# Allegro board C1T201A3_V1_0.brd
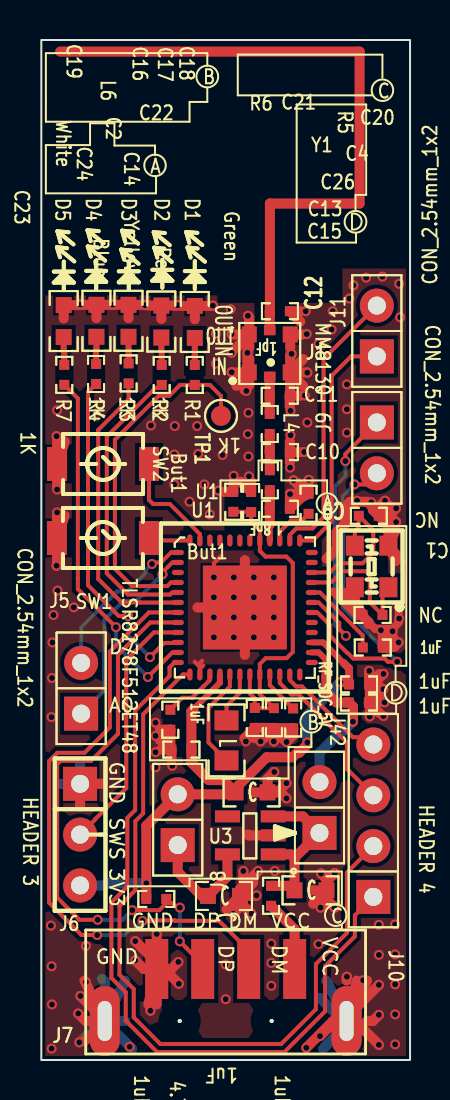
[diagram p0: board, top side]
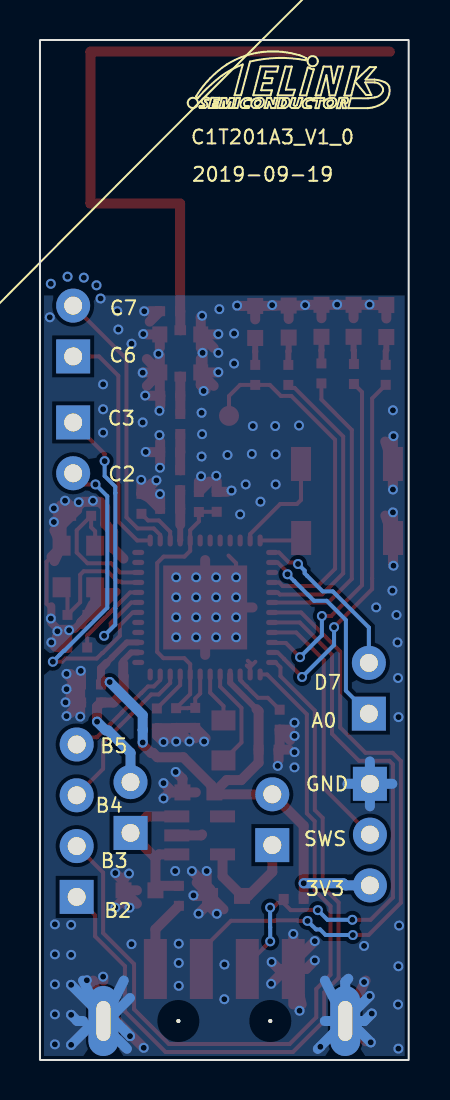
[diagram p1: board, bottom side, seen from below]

Outline 18.45 x 51 mm; copper layers: TOP, BOTTOM. Coordinates in mm from the lower left corner of the outline.
Outline path: rectangle 0,0 18.45,51

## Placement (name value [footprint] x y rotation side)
C1  NC  [0402]  16.39 27.21 0 top
C2  2.2uF  [0402]  10.5 27.9 270 top
C4  NC  [0402]  16.57 22.25 180 top
C9  NC  [0402]  11.94 27.56 180 top
C10  1.2pF  [0402]  11.94 30.39 180 top
C11  2.4pF  [0402]  11.93 33.21 180 top
C12  1pF  [0402]  11.94 37.44 180 top
C13  1uF  [0402]  15.9 18.78 0 top
C14  1uF  [0402]  13.37 27.81 270 top
C15  1uF  [0402]  15.89 17.88 0 top
C16  1uF  [0402]  10.68 17.1 90 top
C17  0.1uF  [0402]  11.64 17.09 90 top
C18  1uF  [0402]  12.6 17.08 270 top
C19  1uF  [0402]  6.46 17.01 90 top
C20  10uF  [0603C]  13.47 8.48 0 top
C21  10uF  [0603C]  9.14 8.2 0 top
C22  10uF  [0603C]  10.52 13.38 0 top
C23  0.1uF  [0402]  9.61 27.91 270 top
C24  220pf  [0402]  11.44 28.99 90 top
C25  1uF  [0402]  7.01 15.52 0 top
C26  1uF  [0402]  16.59 20.62 0 top
D1  Green  [0603-LED]  7.68 36.9 90 top
D2  Red  [0603-LED]  6.01 36.92 90 top
D3  Yellow  [0603-LED]  4.36 36.96 90 top
D4  Blue  [0603-LED]  2.76 36.96 90 top
D5  White  [0603-LED]  1.12 36.95 90 top
J1  MM8130  [MM8130-2600]  11.43 35.33 180 top
J5  CON_2.54mm_1x2  [HDR254F-1X2X850]  1.99 19.86 270 top
J6  HEADER 3  [HDR254M-1X3]  1.94 13.81 270 top
J7  USB_SMT_4PIN  [USB-M-4]  9.22 4.55 90 top
J8  B2S  [HDR254F-1X2X850]  6.83 13.28 270 top
J9  CON_2.54mm_1x2  [HDR254F-1X2X850]  16.79 29.34 90 top
J10  HEADER 4  [HDR254F-1X4X850]  16.61 15.78 270 top
J11  CON_2.54mm_1x2  [HDR254F-1X2X850]  16.79 37.72 270 top
J42  RF_SOC_5V  [HDR254F-1X2X850]  13.92 13.89 270 top
L4  2.4nH  [0402]  11.43 31.8 90 top
L6  4.7uH  [0805L]  9.27 15.98 270 top
R1  1K  [0402]  7.68 34.25 90 top
R2  1K  [0402]  6.02 34.25 90 top
R3  1K  [0402]  4.37 34.33 90 top
R4  1K  [0402]  2.74 34.3 90 top
R5  10  [0402]  11.5 8.21 90 top
R6  NC/1.5K  [0402]  5.75 8.05 0 top
R7  1K  [0402]  1.15 34.26 90 top
SW1  But1  [BUTSMD2PX4_00Y3_00_NH]  3.08 26.1 270 top
SW2  But1  [BUTSMD2PX4_00Y3_00_NH]  3.09 29.8 270 top
TP1  A2  [TP100]  8.99 32.21 0 top
U1  TLSR8278F512ET48  [QFN_7X7_48PIN_0P5_4P20X4P20]  10.18 22.63 0 top
U3  XC6219_3.3V_SOT-23-5  [SOT-23-5]  10.46 11.23 90 top
Y1  24MHz-12pF-+/-20ppm  [OSCCC200X250X080]  16.53 24.68 180 top

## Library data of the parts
C1 C4 = C1005_NC
C2 C13-C15 C23 C24 C26 = C1005X5R1C104K
C9-C12 = C1608_NC
C16 C17 C19 C25 = C1005X5R1C105K
C18 C20-C22 = C1608X5R0J106M
D1-D5 = 0603D_Red
J1 = MM8130
J5 J9 J11 = CON_2.54mm_1x2: User Part Number: pn; Tolerance: RichardLC
J6 = HEADER 3: User Part Number: pn; Tolerance: RichardLC
J7 = USB_SMT_1
J8 = B2S_0: User Part Number: pn; Tolerance: RichardLC
J10 = HEADER_4: User Part Number: pn; Tolerance: RichardLC
J42 = B2S_3: User Part Number: pn; Tolerance: RichardLC
L4 = MLK1608_000R
L6 = IND_0
R1-R4 R7 = RS0402K332JT
R5 R6 = RS0402K100JT
SW1 SW2 = SW2PIN_3x4
TP1 = TestPad100
U1 = TLSR8278F1KET48_2
U3 = XC6219_1.3V_SOT-23-5
Y1 = OSC_25x32_4pin

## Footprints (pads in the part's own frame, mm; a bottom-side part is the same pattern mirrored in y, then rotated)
0402
  rect 0.5x0.5 smd: 1(-0.5,0) 2(0.5,0)
0603-LED
  rect 0.8x0.8 smd: A(-0.8,0) C(0.8,0)
0603C
  rect 0.8x0.8 smd: 1(-0.8,0) 2(0.8,0)
0805L
  rect 1x1.2 smd: 1(-1,0) 2(1,0)
BUTSMD2PX4_00Y3_00_NH
  rect 1.7x1 smd: 1(0,2.3) 2(0,-2.3)
HDR254F-1X2X850
  rect 1.7x1.7 hole 0.9: 1(2.54,0)
  round 1.7 hole 0.9: 2(0,0)
HDR254F-1X4X850
  rect 1.7x1.7 hole 0.9: 1(7.62,0)
  round 1.7 hole 0.9: 2(5.08,0) 3(2.54,0) 4(0,0)
HDR254M-1X3
  rect 1.7x1.7 hole 0.9: 1(0,0)
  round 1.7 hole 0.9: 2(2.54,0) 3(5.08,0)
MM8130-2600
  rect 0.58x0.5 smd: 1(0,1.16) 2(0,-1.16)
  rect 0.75x0.8 smd: 3(-1.025,0.95) 4(1.025,0.95) 5(-1.025,-0.95) 6(1.025,-0.95)
OSCCC200X250X080
  rect 0.9x1 smd: 1(-0.84,1.04) 2(-0.84,-1.04) 3(0.84,-1.04) 4(0.84,1.04)
QFN_7X7_48PIN_0P5_4P20X4P20
  oval 0.6x0.26 smd: 1(-3.35,2.75) 2(-3.35,2.25) 3(-3.35,1.75) 4(-3.35,1.25) 5(-3.35,0.75) 6(-3.35,0.25) 7(-3.35,-0.25) 8(-3.35,-0.75) 9(-3.35,-1.25) 10(-3.35,-1.75) 11(-3.35,-2.25) 12(-3.35,-2.75) 25(3.35,-2.75) 26(3.35,-2.25) 27(3.35,-1.75) 28(3.35,-1.25) 29(3.35,-0.75) 30(3.35,-0.25) 31(3.35,0.25) 32(3.35,0.75) 33(3.35,1.25) 34(3.35,1.75) 35(3.35,2.25) 36(3.35,2.75)
  oval 0.26x0.6 smd: 13(-2.75,-3.35) 14(-2.25,-3.35) 15(-1.75,-3.35) 16(-1.25,-3.35) 17(-0.75,-3.35) 18(-0.25,-3.35) 19(0.25,-3.35) 20(0.75,-3.35) 21(1.25,-3.35) 22(1.75,-3.35) 23(2.25,-3.35) 24(2.75,-3.35) 37(2.75,3.35) 38(2.25,3.35) 39(1.75,3.35) 40(1.25,3.35) 41(0.75,3.35) 42(0.25,3.35) 43(-0.25,3.35) 44(-0.75,3.35) 45(-1.25,3.35) 46(-1.75,3.35) 47(-2.25,3.35) 48(-2.75,3.35)
  rect 4.2x4.2 smd: 49(0,0)
SOT-23-5
  rect 0.6x1.25 smd: 1(-0.95,-1.145) 2(0,-1.145) 3(0.95,-1.145) 4(0.95,1.145) 5(-0.95,1.145)
TP100
  round 1 smd: 1(0,0)
USB-M-4
  round 0.2 hole 1.7 unplated: (-2.6,2.3) (-2.6,-2.3)
  rect 3x1.15 smd: 1(0,-3.45) 2(0,-1.15) 3(0,1.15) 4(0,3.45)
  oval 3.5x1.5 hole 2x0.7: S1(-2.6,6.05) S2(-2.6,-6.05)

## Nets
3V3: C13.1 C22.1 C25.2 J6.3 J8.2 R6.1 U1.16(VDD_IO) U1.27(VDD3)
GND: C1.2 C2.1 C4.2 C9.1 C10.1 C11.1 C12.1 C13.2 C14.1 C15.2 C16.1 C17.1 C18.2 C19.1 C20.2 C21.2 C22.2 C23.1 C25.1 C26.2 D1.C(CATHODE) D2.C(CATHODE) D3.C(CATHODE) D4.C(CATHODE) D5.C(CATHODE) J1.3 J1.4 J1.5 J1.6 J6.1 J7.4(GND) J7.S1 J7.S2 SW1.2 SW2.2 U1.14(DVSS) U1.49(GND) U3.2(VSS) Y1.2 Y1.4
VBUS: C20.1 J42.1 R5.2 U3.1(VIN) U3.3(CE)
TL_1V4: C2.2 C16.2 C17.2 C23.2 U1.19(VDD1V2) U1.20(AVDD1V2#20) U1.41(AVDD1V2#41)
TL_A0: J5.1 U1.2(DMIC_DI/P0N/URX/MDEC/A[0])
TL_A2: R1.1 TP1.1(TP) U1.4(DO/UTX/P0/A[2])
TL_A3: R2.1 U1.5(DI/SDA/UCTS/P1/A[3])
TL_A4: R3.1 U1.6(CK/SCL/URTS/P2/A[4])
TL_ANT: C9.2 C24.1 U1.40(ANT)
TL_B0: R4.1 U1.10(P3/URX/ATSEL1/MDEC/B[0])
TL_B1: R7.1 U1.11(P4/UTX/ATSEL2/B[1])
TL_B2: J10.1 U1.12(P5/UCTS/CYC2LNA/B[2])
TL_B3: J10.2 U1.13(P0N/URTS/CYC2PA/B[3])
TL_B4: J10.3 U1.22(SDMP0/P4/CMP_D/B[4])
TL_B5: J10.4 U1.23(SDMN0/P5/CMP_DF/B[5])
TL_C2: J9.2 U1.30(P0/7816TRX/UTX/SDA/32KO/C[2])
TL_C3: J9.1 U1.31(P1/URX/SCK/32KIN/C[3])
TL_C6: J11.1 U1.37(CYC2LNA/ATSEL1/P4N/C[6])
TL_C7: J11.2 U1.38(CYC2PA/ATSEL2/P5N/C[7])
TL_D5: SW2.1 U1.47(P0/CMP_D/P0N/D[5])
TL_D6: SW1.1 U1.48(CN/URX/ATSEL0/D[6])
TL_D7: J5.2 U1.1(CK/SCL/I2SBCK/7816TRX/UTX/D[7])
TL_DM: J7.2(D-) U1.7(DM/A[5])
TL_DP: J7.3(D+) R6.2 U1.8(DP(SWS)/A[6])
TL_SWS/A7: J6.2 U1.9(SWS/URTS/A[7])
TL_VBUS: C15.1 J42.2 U1.26(VBUS)
TL_XC1: C1.1 U1.34(XC1) Y1.3
TL_XC2: C4.1 U1.33(XC2) Y1.1
N14798367: C18.1 U1.21(VDD_F)
N14798503: C19.2 U1.15(VDD1V)
N14803152: C10.2 C24.2 L4.1
N14803220: C11.2 J1.1 L4.2
N14803264: C12.2 J1.2
N14848024: L6.2 U1.17(VDCDC_SW)
N14849302: C26.1 U1.32(VMID)
N14850032: C14.2 U1.39(RESETB)
N14858611: C21.1 J8.1 U3.5(VOUT)
N14858615: J7.1(5V) R5.1
N14860106: D5.A(ANODE) R7.2
N14860310: D1.A(ANODE) R1.2
N14860350: D3.A(ANODE) R3.2
N14860358: D4.A(ANODE) R4.2
N14860454: D2.A(ANODE) R2.2
N14865099: L6.1 U1.18(VDCDC)

Pads without a net: U1 3 24 25 28 29 35 36 42 43 44 45 46; U3 4

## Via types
v1: diameter 0.5, hole 0.3, TOP to BOTTOM, 175 vias

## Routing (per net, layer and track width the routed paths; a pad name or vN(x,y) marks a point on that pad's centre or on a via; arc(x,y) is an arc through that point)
3V3: length 32.2
  TOP w0.3: U1.27 14.1,20.88 14.85,20.13 14.85,20.13 15.12,19.85 ; U1.16 8.93,18.86 7.62,17.54
  TOP w0.4: 15.12,19.85 15.4,19.58 C13.1
  TOP w0.5: C22.1 9.11,14 8.38,14 7.51,14.87 C25.2 7.51,17.44 7.62,17.54 ; C22.1 9.62,13.28 J8.2 5.25,11.71 v1(5.25,8.84) R6.1 ; C22.1 9.72,13.53 9.87,13.68 9.87,13.73 11.28,15.14 12.57,15.14 12.79,15.36 12.89,15.36 13.3,15.77 13.3,15.87 v1(13.31,15.88) ; C13.1 15.28,18.9 v1(14.96,18.9)
  BOTTOM w0.5: v1(13.31,15.88) 13.31,16.5 13.31,17.25 v1(14.96,18.9) ; J6.3 3.16,8.73 3.27,8.84 v1(5.25,8.84)
GND: length 195.3
  TOP w0.2: v1(8.64,21.13) 8.69,21.13 U1.49 ; 17.87,25.16 18.12,24.92 18.12,22.81 17.99,22.69 17.88,22.69 ; 7.93,19.55 8.1,19.72 ; 7.93,19.55 U1.14 ; 7.93,19.55 7.93,19.65 ; v1(10.64,24.13) v1(9.64,24.13) ; 9.02,25.22 8.64,24.84 v1(8.64,24.13) ; 8.05,19.96 7.93,19.85 7.93,19.65 ; v1(11.64,22.13) v1(11.64,21.13) v1(10.64,22.13) ; 7.93,19.65 7.67,19.91 ; v1(8.64,23.13) v1(8.64,22.13)
  TOP w0.4: 16.45,17.88 16.44,17.88 ; 16.45,17.88 v1(17.12,18.54) 16.88,18.78 16.59,18.78 ; 16.45,17.88 17.16,17.88 v1(17.17,17.88) 16.4,18.65 C13.2 16.39,18.77 C15.2 ; 16.44,17.88 C15.2 ; 16.44,17.88 v1(17.12,17.2) ; C15.2 16.39,17.21 v1(16.43,17.17) ; 15.85,22.25 15.77,22.25 14.61,23.42 ; 17.88,22.69 17.88,21.87 17.57,21.56 16.71,21.56 16.42,21.84 16.42,21.9 C4.2
  TOP w0.5: v1(17.75,26.9) 17.44,27.21 17.38,27.21 ; 5.78,4.55 5.46,4.24 v1(5.46,2.46) ; 5.78,4.55 5.13,4.55 v1(4.7,4.98) ; 5.78,4.55 5.35,2.78 ; 5.78,4.55 6.14,4.55 ; 5.78,4.55 5.78,2.78 ; 5.78,4.55 5.78,4.87 ; 13.3,28.31 12.45,28.31 v1(12.45,28.3) ; 13.3,28.31 v1(12.62,28.98) ; 13.3,28.31 C14.1 ; C16.1 11.63,16.6 C17.1 ; C16.1 10.16,16.08 ; C16.1 10.68,16.08 ; J1.6 10.31,36.19 v1(10.31,35.36) 10.31,34.47 J1.4 ; J1.6 9.76,35.61 ; J1.6 10.4,35.61 ; J1.6 9.54,36.28 v1(9.53,36.3) ; J1.6 10.4,37.14 v1(10.34,37.21) ; J1.4 10.4,35.05 ; J1.4 10.4,33.75 10.16,33.5 ; J1.4 9.54,34.38 v1(9.53,34.39) ; J1.4 9.76,33.71 ; v1(14,9.32) 14.27,9.05 ; 14.27,9.05 C20.2 ; 14.27,9.05 14.38,9.05 v1(14.68,9.35) ; 15.28,1.95 16.3,3.97 ; 15.28,1.95 15.79,3.97 ; 15.28,1.95 14.7,1.95 ; 15.28,1.95 15.7,1.95 v1(16.89,0.76) ; 0.79,28.68 SW2.2 ; SW2.2 1.18,30.92 ; SW2.2 0.79,31.16 v1(0.76,31.19) ; v1(6.83,37.74) 6.81,37.72 D2.C ; SW1.2 0.78,24.73 v1(0.76,24.71) ; SW1.2 0.78,27.22 ; SW1.2 1.17,27.22 ; 12.08,16.06 C18.2 ; C18.2 12.34,16.06 ; C18.2 12.59,16.59 C17.1 ; C18.2 12.6,16.23 v1(12.27,15.9) ; J1.3 12.45,33.24 C11.1 ; J1.3 13.1,33.71 ; J1.3 13.1,35.05 ; J1.3 13.3,34.38 v1(13.31,34.37) ; J1.3 12.45,35.24 v1(12.52,35.31) ; Y1.2 17.73,24.95 ; Y1.2 17.37,26.73 C1.2 ; Y1.2 17.37,25.67 17.87,25.16 ; Y1.2 17.73,26.49 ; 16.39,21.8 16.37,21.82 16.37,21.89 16.07,22.19 C4.2 ; 17.09,20.95 C26.2 ; 17.09,20.95 v1(17.58,21.44) ; 17.09,20.95 17.09,21.39 v1(16.99,21.49) ; C26.2 17.47,20.62 17.51,20.66 17.67,20.66 v1(17.88,20.88) ; C26.2 17.61,21.14 ; C26.2 17.35,21.14 ; v1(11.66,14.4) 11.32,14.06 C22.2 ; 13.1,36.28 J1.5 12.45,35.61 ; 5.94,15.99 C19.1 ; C19.1 6.46,15.57 C25.1 ; C19.1 5.94,16.51 ; 15.69,22.87 Y1.4 ; Y1.4 15.39,23.34 ; Y1.4 15.33,22.87 ; 12.85,28.83 C14.1 ; C14.1 12.85,28.05 ; C14.1 13.37,28.99 v1(13.39,29.01) ; 7.81,22.63 U1.49 ; U1.49 10.18,20.26 ; U1.49 10.18,25 ; 15.39,23.34 14.86,23.34 ; 15.39,23.34 15.34,23.29 15.34,22.76 15.85,22.25 C4.2 ; 6.14,4.55 6.51,4.55 v1(6.86,4.9) ; 6.14,4.55 v1(6.88,3.81) ; v1(12.27,13.84) 11.81,13.38 C22.2 ; 14.27,8.03 C20.2 ; 14.27,8.03 v1(14.68,7.62) ; 14.27,8.03 14.27,7.92 v1(13.97,7.62) ; C20.2 13.6,8.48 ; C20.2 13.6,7.81 ; 5.78,4.87 v1(5.78,6.3) ; 5.78,4.87 v1(4.7,5.94) ; C10.1 12.96,30.39 ; C10.1 12.44,29.87 ; C10.1 12.44,30.92 ; 2.15,0.94 J7.S1 ; J7.S1 2.22,1.95 v1(1.85,2.32) ; J7.S1 2.15,3.97 ; C13.2 16.4,19.45 v1(16.41,19.46) ; C13.2 16.59,18.78 v1(17.12,19.3) ; C13.2 16.92,18.26 ; C13.2 16.92,19.3 ; 12.96,36.92 C12.1 12.96,37.44 ; v1(9.6,7.32) 9.94,7.65 9.94,7.89 ; 10.11,8.71 v1(10.11,9.45) ; 10.11,8.71 9.94,8.54 C21.2 ; 10.11,8.71 v1(10.85,9.45) ; 7.68,37.03 D1.C ; D1.C 7.01,37.7 ; D1.C 8.57,37.7 v1(8.59,37.72) ; 14.7,1.95 14.6,1.95 v1(13.26,0.61) ; 14.7,1.95 v1(13.94,1.19) ; 16.91,18.4 C15.2 16.91,17.35 ; 12.43,32.69 C11.1 ; C11.1 12.95,33.21 ; 14.27,25.07 14.79,25.58 14.79,26.4 15.19,26.8 15.19,27.64 15.45,27.91 16.33,27.91 16.59,27.64 16.59,27.51 C1.2 ; C4.2 15.81,22.77 ; C4.2 15.55,22.77 ; 3.06,13.81 J6.1 1.94,12.69 ; 10.34,11.28 10.39,11.23 U3.2 ; 5.99,15.52 C25.1 ; C25.1 6.51,15 ; 9.09,28.41 C23.1 9.61,28.93 ; v1(16.89,2.26) 16.58,1.95 16.3,1.95 ; C1.2 17.15,27.73 ; C1.2 16.89,27.66 v1(17.2,27.97) ; C1.2 17.38,27.21 ; C1.2 17.41,27.73 ; C17.1 11.64,15.93 v1(11.63,15.93) ; C17.1 12.16,16.07 ; C17.1 11.12,16.07 ; 9.27,7.53 C21.2 ; C21.2 10.74,8.2 v1(10.77,8.23) ; C21.2 10.61,8.87 ; C21.2 9.94,7.89 ; 10.5,28.92 C2.1 9.98,28.92 ; 10.65,13.38 C22.2 ; v1(5.18,37.74) 5.17,37.76 D3.C ; 17.38,27.21 v1(17.75,27.58) ; D4.C 1.97,37.76 v1(1.96,37.77) 1.93,37.75 D5.C 1.12,37.08 ; D4.C 3.57,37.76 v1(3.58,37.77) ; D4.C 2.76,37.09 ; 3.69,37.76 D3.C ; D3.C 4.36,37.09 ; D2.C 5.34,37.72 ; D2.C 6.01,37.05 ; 15.28,2.14 v1(16.89,3.76) ; v1(15.29,4.17) 15.28,4.15 15.28,3.97 ; 3.17,1.98 v1(1.96,3.2) ; v1(10.52,7.32) 9.94,7.89 ; 12.96,28.08 C9.1 12.44,28.08 ; 11.97,13.38 v1(12.27,13.08)
  BOTTOM w0.5: 4.55,0.55 3.17,1.92 J7.S1 ; v1(16.89,3.76) 15.28,2.14 15.28,1.95 ; v1(16.89,0.76) 15.7,1.95 15.28,1.95 ; 15.28,1.95 16.3,3.97 ; 15.28,1.95 15.09,1.95 ; 15.28,1.95 14.25,3.97 ; 15.28,1.95 15.28,1.74 14.1,0.56 ; 15.09,1.95 13.94,3.1 ; 15.09,1.95 14.7,1.95 v1(13.94,1.19) ; v1(16.89,2.26) 16.58,1.95 16.3,1.95 ; J7.S1 4.2,3.97 ; J7.S1 4.2,1.95 ; J7.S1 2.97,1.95 ; J7.S1 3.17,1.98 ; J6.1 1.94,14.93 ; J6.1 3.06,13.81 ; J6.1 0.82,13.81 ; J6.1 1.94,12.69 ; 3.02,4.06 3.17,3.91 3.17,1.98 ; 2.97,1.95 2.22,1.95 v1(1.85,2.32) ; 2.97,1.95 v1(1.9,0.88) ; v1(1.96,3.2) 3.17,1.98
  vias: v1(0.53,19.1) v1(0.51,17.14) v1(0.48,6.72) v1(0.51,4.69) v1(0.53,2.78) v1(0.51,0.57) v1(0.61,22.25) v1(0.56,20.88) v1(0.79,32.49) v1(0.79,28.52) v1(0.79,27.38) v1(0.81,23.47) v1(1.63,22.63) v1(2.23,5.7) v1(2.23,3.9) v1(4.42,0.66) v1(5.49,31.72) v1(5.71,16.87) v1(5.71,16.21) v1(5.71,15.39) v1(5.71,14.63) v1(6.55,14.71) v1(6.68,31.7) v1(6.65,30.28) v1(6.65,28.78) v1(7.42,27.91) v1(7.8,31.7) v1(7.85,30.3) v1(8.15,28.78) v1(8.43,27.28) v1(8.74,36.32) v1(8.74,34.82) v1(8.86,28.47) v1(9.07,30.25) v1(9.22,4.78) v1(9.23,3.04) v1(9.47,37.54) v1(9.53,35.36) v1(9.63,29.21) v1(9.64,23.13) v1(9.64,22.13) v1(9.64,21.13) v1(10.24,15.93) v1(10.26,33.45) v1(10.34,31.29) v1(10.36,32.36) v1(10.36,30.18) v1(10.39,29.18) v1(10.64,23.13) v1(10.64,21.13) v1(10.97,15.93) v1(11.51,5.82) v1(11.51,4.85) v1(11.51,3.71) v1(11.64,24.13) v1(11.64,23.13) v1(11.68,9.45) v1(12.45,29.62) v1(12.47,32.46) v1(12.47,31.24) v1(13.23,37.44) v1(13.18,33.22) v1(13.16,30.4) v1(13.28,36.3) v1(13.31,31.88) v1(13.87,35.81) v1(13.87,5.79) v1(14.53,36.53) v1(14.58,37.44) v1(15.29,33.78) v1(15.29,32.54) v1(15.29,31.37) v1(15.42,38.07) v1(15.62,38.73) v1(15.8,27.97) v1(16.1,3.99) v1(16.26,39.12) v1(16.51,27.89) v1(16.89,6.76) v1(16.89,5.26) v1(17.07,39.17) v1(17.7,6.78) v1(17.7,5.28) v1(17.7,3.78) v1(17.7,2.28) v1(17.7,0.78) v1(17.91,38.81) v1(17.91,22.07) v1(17.96,37.13)
VBUS: length 8.4
  TOP w0.5: 12.67,10.1 J42.1 13.09,12.18 U3.3 ; 12.67,10.1 12.49,10.28 U3.1 ; 12.67,10.1 C20.1 12.44,8.71 R5.2
TL_1V4: length 16.5
  TOP w0.2: C23.2 10.49,27.41 C2.2 10.5,26.93 10.93,26.49 U1.41 10.93,25.46 11.22,25.17 12.26,25.17 12.58,24.85 12.58,20.4 12.27,20.09 11.23,20.09 10.93,19.8 U1.20 10.93,18.3 C17.2 11.05,17.59 11.04,17.6 C16.2 10.68,18.07 10.43,18.32 U1.19
TL_A0: length 10.1
  TOP w0.2: v1(6.06,24.29) 6.06,24.38 6.56,24.88 U1.2
  BOTTOM w0.2: v1(6.06,24.29) 5.73,23.95 5.73,23.95 4.74,22.96 4.11,22.96 3.14,22 3.14,18.47 J5.1
TL_A2: length 17.7
  TOP w0.2: U1.4 6.48,23.88 6.31,23.7 4.55,23.7 3.68,24.56 3.68,31.01 5.87,33.2 6.4,33.2 6.95,33.75 R1.1 8.43,33.75 8.99,33.2 TP1.1
TL_A3: length 14.7
  TOP w0.2: U1.5 6.55,23.38 6.45,23.27 5.12,23.27 5.11,23.28 4.33,23.28 3.28,24.33 3.28,31.17 5.71,33.6 5.87,33.6 R2.1
TL_A4: length 14.9
  TOP w0.2: U1.6 6.61,22.88 6.61,22.87 4.95,22.87 4.95,22.88 4.02,22.88 2.84,24.05 2.84,31.5 4.37,33.03 R3.1
TL_ANT: length 3.4
  TOP w0.3: U1.40 11.43,25.98 11.43,26.77
  TOP w0.5: C9.2 11.44,28.49 C24.1 11.44,27.57 11.43,27.56 11.43,26.77
TL_B0: length 17.1
  TOP w0.2: v1(5.44,20.14) 6.15,20.85 6.61,20.85 6.63,20.88 U1.10 ; v1(4.34,22.2) 3.87,22.2 2.33,23.74 2.33,33.4 R4.1
  BOTTOM w0.2: v1(4.34,22.2) 4.34,21.23 v1(5.44,20.14)
TL_B1: length 18.3
  TOP w0.2: R7.1 1.83,33.08 1.83,24.08 1.83,23.55 v1(3.73,21.64) ; v1(5.33,19.15) 6.23,20.05 6.23,20.05 6.56,20.38 U1.11
  BOTTOM w0.2: v1(5.33,19.15) 3.73,20.75 v1(3.73,21.64)
TL_B2: length 37.9
  TOP w0.2: U1.12 6.66,19.88 6.42,19.63 6.42,19.19 4.7,17.47 4.7,12.5 4.3,12.11 4.3,8.67 3.51,7.87 3.51,4.1 4.22,3.38 4.22,1.97 5.79,0.4 12.17,0.4 14.2,2.43 14.2,4.69 15.69,6.18 15.69,7.23 J10.1
TL_B3: length 38.8
  TOP w0.2: U1.13 7.08,19.28 5.1,17.29 5.1,12.33 4.7,11.94 4.7,8.49 3.91,7.7 3.91,4.26 4.62,3.55 4.62,2.13 5.96,0.8 12,0.8 13.74,2.54 13.74,4.8 15.29,6.35 15.29,9.37 J10.2
TL_B4: length 8.2
  TOP w0.2: U1.22 11.93,18.85 12.51,18.28 12.88,18.28 13.28,17.88 13.29,17.88 13.94,17.22 13.94,17.22 14.42,16.74 14.73,16.43 14.74,16.43 15.29,15.88 15.29,15.74 15.29,14.56 J10.3
TL_B5: length 5.8
  TOP w0.2: J10.4 16.25,16.14 15.59,16.14 14.9,16.83 14.9,16.83 14.36,17.36 14.36,17.37 13.38,18.35 13.38,18.35 13.05,18.68 12.76,18.68 12.43,19 U1.23
TL_C2: length 17.2
  TOP w0.2: v1(15.67,28.78) 16.23,28.78 J9.2 ; v1(17.81,19.91) 17.34,19.91 17.17,20.07 15.61,20.07 15.33,20.35 15.31,20.35 14.45,21.21 14.45,21.74 13.81,22.38 U1.30
  BOTTOM w0.2: v1(17.81,19.91) 17.47,20.25 17.25,20.47 17.23,20.47 15.08,22.61 15.08,28.19 v1(15.67,28.78)
TL_C3: length 14.3
  TOP w0.2: J9.1 15.21,30.3 v1(15.21,29.95) ; v1(15.24,21.21) 14.91,21.54 14.91,21.85 13.88,22.88 U1.31
  BOTTOM w0.2: v1(15.24,21.21) 14.68,21.77 14.68,22.57 14.68,22.57 14.68,28.35 14.68,28.35 14.68,28.67 15.21,29.2 v1(15.21,29.95)
TL_C6: length 11.9
  TOP w0.2: J11.1 15.49,35.18 14.53,34.21 14.53,26.92 13.58,25.98 U1.37
TL_C7: length 14
  TOP w0.2: U1.38 12.43,26.25 12.76,26.58 13.56,26.58 14.12,27.13 14.12,35.05 J11.2
TL_D5: length 5.4
  TOP w0.2: SW2.1 5.39,28 5.59,27.8 6.43,27.8 7.93,26.3 U1.47
TL_D6: length 2.1
  TOP w0.2: U1.48 5.49,25.98 5.38,26.09 SW1.1
TL_D7: length 8.2
  TOP w0.2: v1(5.54,24.8) 5.61,24.87 5.99,24.87 6.49,25.38 U1.1
  BOTTOM w0.2: J5.2 1.99,21.63 3.8,23.43 4.31,23.43 5.08,24.21 5.08,24.21 5.2,24.33 5.2,24.47 v1(5.54,24.8)
TL_DM: length 31.3
  TOP w0.2: v1(2.79,6.25) 2.32,6.25 2.32,6.25 2,6.25 0.39,7.86 0.39,14.95 0.8,15.36 2.16,15.36 3.43,16.63 3.43,20.42 5.38,22.38 U1.7 ; J7.2 10.38,5.47 8.89,6.96 6.7,6.96 6.67,6.99 5.56,6.99 5.53,6.95 v1(5.06,6.95)
  BOTTOM w0.2: v1(2.79,6.25) 4.15,6.25 4.43,6.53 4.64,6.53 v1(5.06,6.95)
TL_DP: length 28.8
  TOP w0.2: J7.3 8.07,4.78 7.26,5.59 7.26,5.6 v1(6.93,5.93) ; 6.25,7.84 6.56,7.84 6.78,7.62 v1(6.93,7.62) ; 6.25,7.84 R6.2 ; 6.25,7.84 5.9,7.49 5.34,7.49 5.33,7.5 4.79,7.5 4.78,7.49 v1(4.55,7.49) ; v1(2.82,7.01) 1.91,7.01 0.79,8.13 0.79,14.78 0.97,14.96 2.49,14.96 3.84,16.31 3.84,20.26 5.45,21.88 U1.8
  BOTTOM w0.2: v1(4.55,7.49) 4.06,7.01 v1(2.82,7.01) ; v1(6.93,5.93) 6.93,6.63 6.93,6.64 v1(6.93,7.62)
TL_SWS/A7: length 12.8
  TOP w0.2: J6.2 2.7,12.03 2.7,12.04 4.25,13.6 4.25,20 5.63,21.38 U1.9
TL_VBUS: length 8.7
  TOP w0.3: U1.26 13.88,20.38 14.28,19.97 14.28,19.81
  TOP w0.5: 14.28,19.81 14.28,19.21 14.26,19.19 14.26,18.61 14.28,18.58 14.28,18.36 14.77,17.88 C15.1 15.59,17.67 v1(15.59,16.92)
  BOTTOM w0.5: v1(15.59,16.92) 15.16,16.48 15.04,16.48 13.92,15.36 J42.2
TL_XC1: length 7.2
  TOP w0.2: U1.34 14.44,24.38 14.9,24.84 16.07,24.84 16.61,25.37 16.61,26.49 C1.1 15.89,26.64 15.69,26.44 Y1.3
TL_XC2: length 7
  TOP w0.2: Y1.1 17.07,23.34 C4.1 16.44,22.89 16.44,24.26 16.26,24.44 15.06,24.44 14.55,23.92 14.4,23.92 14.36,23.88 U1.33
N14798367: length 2.2
  TOP w0.2: C18.1 11.43,18.74 U1.21
N14798503: length 2.9
  TOP w0.2: C19.2 7.05,18.11 7.54,18.11 8.11,18.68 8.11,18.68 8.36,18.93 8.36,18.93 8.43,19 U1.15
N14803152: length 1.8
  TOP w0.5: L4.1 11.43,30.4 C10.2 C24.2
N14803220: length 1.9
  TOP w0.5: J1.1 C11.2 L4.2
N14803264: length 33.4
  TOP w0.5: J1.2 11.43,37.44 C12.2 11.44,42.82 15.93,42.82 15.93,50.42 0.94,50.42
N14848024: length 5.1
  TOP w0.2: L6.2 8.37,15.88 8.37,17.6 9.43,18.67 U1.17
N14849302: length 4
  TOP w0.2: U1.32 13.94,23.38 15.02,22.3 15.64,21.68 15.64,21.67 16.09,21.23 C26.1
N14850032: length 2.2
  TOP w0.2: C14.2 13.04,26.98 12.5,26.98 11.93,26.41 U1.39
N14858611: length 5.8
  TOP w0.5: J8.1 6.83,9.41 8.03,8.2 C21.1 9.31,9.18 U3.5
N14858615: length 3.6
  TOP w0.5: J7.1 12.68,6.53 R5.1
N14860106: length 1.4
  TOP w0.3: R7.2 1.15,35.45 1.12,35.48 D5.A
N14860310: length 1.3
  TOP w0.3: R1.2 7.68,35.43 7.68,35.43 D1.A
N14860350: length 1.3
  TOP w0.3: R3.2 4.37,35.48 4.36,35.49 D3.A
N14860358: length 1.4
  TOP w0.3: R4.2 2.74,35.47 2.76,35.49 D4.A
N14860454: length 1.4
  TOP w0.3: R2.2 6.02,35.43 6.01,35.45 D2.A
N14865099: length 2.6
  TOP w0.2: U1.18 9.93,18.37 9.27,17.7 L6.1

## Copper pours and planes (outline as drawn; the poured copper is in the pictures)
GND on TOP: 14.43,28.32 14.43,25.17 15.34,25.17 15.34,28.32
GND on TOP: 0.2,0.2 0.2,38.23 8.81,38.23 8.81,37.85 10.67,37.85 10.67,33.86 10.68,33.86 10.68,28.4 10.57,28.4 10.57,27.74 12.18,27.74 12.18,33.02 12.19,33.02 12.19,33.91 11.1,33.91 11.1,34.34 12.19,34.34 12.19,36.14 11.1,36.14 11.1,37.85 15.06,37.85 15.06,39.57 18.25,39.57 18.25,0.2 ; 20 cut-outs
GND on BOTTOM: 0.2,0.2 0.2,38.23 18.25,38.23 18.25,0.2 ; 1 cut-out

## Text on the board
Ref Des/Silkscreen Bottom: D7 | A0 | GND | 3V3 | SWS | 2019-09-19 | C1T201A3_V1_0 | C7 | C6 | C2 | C3 | B2 | B3 | B5 | B4
Ref Des/Silkscreen Top: A | B | C | D7 | A0 | GND | SWS | 3V3
COMPVAL_TYPE_TOP: A | B | Chip log:TLSR8278F1KET48 ZHU1933 EP7167.71 | Component manufacturer:Murata
User.6: FIGURE | SIZE | 0.3 | 0.9 | 1.7 | 2.0x0.7 | DRILL CHART: TOP to BOTTOM | ALL UNITS ARE IN MILLIMETERS | PLATED | NON-PLATED | QTY | 175 | 17 | 2
